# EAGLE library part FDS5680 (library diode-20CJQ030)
60V N-Channel PowerTrench TM MOSFET FAIRCHILD FDS5680.pdf
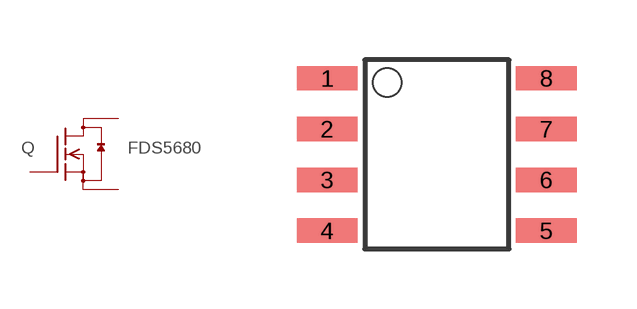
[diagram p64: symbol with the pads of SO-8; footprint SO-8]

Designator prefix Q

## FDS5680  [SO-8]
1  S  pas
2  S  pas
3  S  pas
4  G  pas
5  D  pas
6  D  pas
7  D  pas
8  D  pas

## Footprint SO-8 (pad centres in mm)
small outline
smd 1.524 x 0.61: 1 -2.743,1.27; 2 -2.743,0; 3 -2.743,-1.27; 4 -2.743,-2.54; 5 2.743,-2.54; 6 2.743,-1.27; 7 2.743,0; 8 2.743,1.27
